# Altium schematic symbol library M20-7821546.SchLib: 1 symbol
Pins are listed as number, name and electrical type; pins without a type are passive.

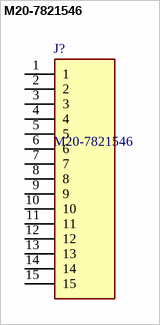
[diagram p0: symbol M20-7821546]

## M20-7821546
designator J?
M20: 15 Pos Receptacle SIL Straight 3mm THT Connector 8.5mm high Tin; Manufacturer_Name: Harwin
footprint RHDR15W70P0X254_1X15_3850X250X850P
pins: 1, 2, 3, 4, 5, 6, 7, 8, 9, 10, 11, 12, 13, 14, 15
